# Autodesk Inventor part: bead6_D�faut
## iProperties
Created: 2011-01
Part Number: bead6_D�faut
Document SubType Name: Modeling
Designer: eric
Density: 1 g/cm^3
Mass: 0.244938 g
Surface Area: 6.80389 cm^2
Volume: 0.244938 cm^3
Author: eric
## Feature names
1. Base1
